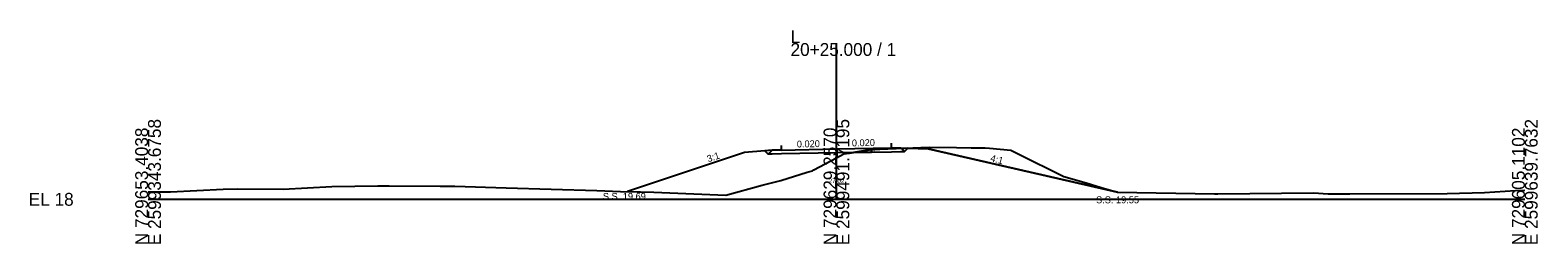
# Model space of a CAD drawing. Extents: x -26 to 3303, y -10 to 9555.
# Drawn here: x 1974.3 to 2302.8, y 490.3 to 536.8 of the extents above; entities that cross this region are included whole.
import ezdxf

# ---------------------------------------------------------------- set-up
doc = ezdxf.new("R2010")
doc.units = 0
for name, color, linetype in [('Exist Cross Section Cell', 7, 'Continuous'), ('Exist XS Center Line Elevation Label', 7, 'Continuous'), ('Exist XS Ground Line', 7, 'Continuous'), ('Prop XS Ditch Slope Text', 7, 'Continuous'), ('Prop XS Dump Level', 7, 'Continuous'), ('Prop XS Earthwork Shape', 7, 'Continuous'), ('Prop XS EOT Tick Mark', 7, 'Continuous'), ('Prop XS Finish Grade', 7, 'Continuous'), ('Prop XS Finish Grade Earthwork', 7, 'Continuous'), ('Prop XS Finish Grade Paved Shoulder', 7, 'Continuous'), ('Prop XS Finish Grade Pavement', 7, 'Continuous'), ('Prop XS Pvmt Edge Slope', 7, 'Continuous'), ('Prop XS SE Text', 7, 'Continuous'), ('Prop XS Side Slope Text', 7, 'Continuous'), ('Prop XS SS Elevation Text', 7, 'Continuous'), ('Prop XS Subgrade Earthwork', 7, 'Continuous')]:
    doc.layers.add(name, color=color, linetype=linetype)

msp = doc.modelspace()

# ---------------------------------------------------------------- linework, layer by layer
at = {"layer": 'Exist Cross Section Cell'}
for p, q in [((2150, 500), (2150, 534.01)), ((2000, 500), (2150, 500)), ((2150, 500), (2300, 500))]:
    msp.add_line(p, q, dxfattribs=at)
at = {"layer": 'Exist XS Ground Line'}
msp.add_lwpolyline([(2000, 501.59), (2004.86, 501.6), (2016.33, 502.17), (2019.5, 502.29), (2029.47, 502.21), (2040.01, 502.77), (2050.1, 502.91), (2052.55, 502.93), (2063.68, 502.86), (2066.82, 502.84), (2078.06, 502.46), (2087.86, 502.22), (2097.82, 501.88), (2102.91, 501.72), (2110.23, 501.55), (2125.87, 500.92), (2133.83, 503.06), (2137.91, 504.1), (2143.59, 505.87), (2144.75, 506.21), (2145.1, 506.41), (2150, 509.02), (2151.6, 509.86), (2152.84, 510.04), (2157.67, 510.86), (2170.18, 511.34), (2176.15, 511.26), (2179.39, 511.22), (2182.43, 511.18), (2183.36, 511.11), (2188, 510.67), (2189.59, 509.92), (2199.56, 504.95), (2204.44, 503.56), (2207.69, 502.56), (2211.27, 501.55), (2232.38, 501.21), (2233.1, 501.2), (2253.92, 501.37), (2257.15, 501.17), (2261.89, 501.19), (2283.06, 501.23), (2291.2, 501.48), (2297.97, 501.91), (2300, 501.97)], dxfattribs=at)
at = {"layer": 'Prop XS Dump Level'}
for p, q in [((2138, 510.71), (2150, 510.95)), ((2150, 510.95), (2162, 511.19))]:
    msp.add_line(p, q, dxfattribs=at)
at = {"layer": 'Prop XS Earthwork Shape'}
for points in [[(2110.23, 501.55), (2125.87, 500.92), (2133.83, 503.06), (2137.91, 504.1), (2143.59, 505.87), (2144.75, 506.21), (2145.1, 506.41), (2150, 509.02), (2151.6, 509.86), (2152.84, 510.04), (2153.71, 510.19), (2150, 510.11), (2138, 509.87), (2136, 509.83), (2135.15, 509.82), (2134.43, 510.54), (2130, 510.19), (2126.91, 509.16), (2104.5, 501.69)], [(2151.6, 509.86), (2152.84, 510.04), (2153.71, 510.19), (2150, 510.11), (2138, 509.87), (2136, 509.83), (2135.15, 509.82), (2134.43, 510.54), (2130, 510.19), (2126.91, 509.16), (2104.5, 501.69), (2110.23, 501.55), (2125.87, 500.92), (2133.83, 503.06), (2137.91, 504.1), (2143.59, 505.87), (2144.75, 506.21), (2145.1, 506.41), (2150, 509.02)], [(2153.71, 510.19), (2157.67, 510.86), (2157.67, 510.27)], [(2157.67, 510.27), (2157.67, 510.86), (2153.71, 510.19)], [(2162, 510.35), (2164, 510.39), (2164.82, 510.41), (2165.57, 511.16), (2157.67, 510.86), (2157.67, 510.27)], [(2157.67, 510.27), (2162, 510.35), (2164, 510.39), (2164.82, 510.41), (2165.57, 511.16), (2157.67, 510.86)], [(2176.15, 511.26), (2179.39, 511.22), (2182.43, 511.18), (2183.36, 511.11), (2188, 510.67), (2189.59, 509.92), (2199.56, 504.95), (2204.44, 503.56), (2207.69, 502.56), (2211.27, 501.55), (2174.16, 510.04), (2170, 510.99), (2165.57, 511.16), (2170.18, 511.34)], [(2170.18, 511.34), (2176.15, 511.26), (2179.39, 511.22), (2182.43, 511.18), (2183.36, 511.11), (2188, 510.67), (2189.59, 509.92), (2199.56, 504.95), (2204.44, 503.56), (2207.69, 502.56), (2211.27, 501.55), (2174.16, 510.04), (2170, 510.99), (2165.57, 511.16)]]:
    msp.add_lwpolyline(points, close=True, dxfattribs=at)
at = {"layer": 'Prop XS EOT Tick Mark'}
for p, q in [((2138, 510.71), (2138, 511.71)), ((2162, 511.19), (2162, 512.19))]:
    msp.add_line(p, q, dxfattribs=at)
at = {"layer": 'Prop XS Finish Grade'}
for p, q in [((2136, 510.67), (2134.43, 510.54)), ((2164, 511.23), (2165.57, 511.16))]:
    msp.add_line(p, q, dxfattribs=at)
at = {"layer": 'Prop XS Finish Grade Earthwork'}
for p, q in [((2130, 510.19), (2126.91, 509.16)), ((2134.43, 510.54), (2130, 510.19)), ((2165.57, 511.16), (2170, 510.99)), ((2170, 510.99), (2174.16, 510.04)), ((2174.16, 510.04), (2211.27, 501.55)), ((2126.91, 509.16), (2104.5, 501.69))]:
    msp.add_line(p, q, dxfattribs=at)
at = {"layer": 'Prop XS Finish Grade Paved Shoulder'}
for p, q in [((2138, 510.71), (2136, 510.67)), ((2162, 511.19), (2164, 511.23))]:
    msp.add_line(p, q, dxfattribs=at)
at = {"layer": 'Prop XS Finish Grade Pavement'}
for p, q in [((2138, 510.71), (2150, 510.95)), ((2150, 510.95), (2162, 511.19))]:
    msp.add_line(p, q, dxfattribs=at)
at = {"layer": 'Prop XS Pvmt Edge Slope'}
for p, q in [((2135.15, 509.82), (2134.43, 510.54)), ((2136, 510.67), (2135.15, 509.82)), ((2164, 511.23), (2164.82, 510.41)), ((2164.82, 510.41), (2165.57, 511.16))]:
    msp.add_line(p, q, dxfattribs=at)
at = {"layer": 'Prop XS Subgrade Earthwork'}
for p, q in [((2135.15, 509.82), (2134.43, 510.54)), ((2136, 509.83), (2135.15, 509.82)), ((2138, 509.87), (2136, 509.83)), ((2150, 510.11), (2138, 509.87)), ((2157.67, 510.27), (2150, 510.11)), ((2157.67, 510.27), (2157.67, 510.86)), ((2157.67, 510.27), (2157.67, 510.86)), ((2157.67, 510.27), (2162, 510.35)), ((2162, 510.35), (2164, 510.39)), ((2164, 510.39), (2164.82, 510.41)), ((2164.82, 510.41), (2165.57, 511.16))]:
    msp.add_line(p, q, dxfattribs=at)

# ---------------------------------------------------------------- texts
at = {"layer": 'Exist Cross Section Cell'}
for s, p in [('L', (2140, 534.01)), ('20+25.000 / 1', (2140, 531.21)), ('EL 18', (1974, 498.6))]:
    msp.add_text(s, height=2.8, dxfattribs=at).set_placement(p)
for s, p in [('E 2599343.6758', (2002.8, 490)), ('E 2599491.7195', (2152.8, 490)), ('E 2599639.7632', (2302.8, 490)), ('N 729653.4038', (2000, 490)), ('N 729629.2570', (2150, 490)), ('N 729605.1102', (2300, 490))]:
    msp.add_text(s, height=2.8, rotation=90, dxfattribs=at).set_placement(p)
at = {"layer": 'Exist XS Center Line Elevation Label'}
msp.add_text('27.02', height=1, dxfattribs=at).set_placement((2148.29, 503.52))
at = {"layer": 'Prop XS Ditch Slope Text'}
msp.add_text('4:1', height=1.5, rotation=344.9182, dxfattribs=at).set_placement((2183.43, 508.32))
at = {"layer": 'Prop XS Dump Level'}
for s, height, p in [('Case1', 0.04, (2130, 510.15)), ('Eop', 0.3, (2157.67, 510.56)), ('Eop', 0.3, (2157.67, 510.56)), ('Case1', 0.04, (2170, 510.95))]:
    msp.add_text(s, height=height, dxfattribs=at).set_placement(p)
at = {"layer": 'Prop XS SE Text'}
for p in [(2141.38, 511.27), (2153.38, 511.51)]:
    msp.add_text('0.020', height=1.5, rotation=1.1458, dxfattribs=at).set_placement(p)
at = {"layer": 'Prop XS Side Slope Text'}
msp.add_text('3:1', height=1.5, rotation=18.4349, dxfattribs=at).set_placement((2122.07, 508.04))
at = {"layer": 'Prop XS SS Elevation Text'}
for s, p in [('S.S. 19.69', (2099.1, 499.88)), ('S.S. 19.55', (2206.57, 499.14))]:
    msp.add_text(s, height=1.5, dxfattribs=at).set_placement(p)

doc.saveas('drawing.dxf')
